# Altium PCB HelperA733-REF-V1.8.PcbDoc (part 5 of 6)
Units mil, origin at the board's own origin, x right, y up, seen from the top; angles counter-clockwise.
Board outline 5905.51 x 4133.86 mil, 2 copper layers (Top, Bottom), stack 12.7 mil thick; 475 components, 355 nets, 1867 pads, 1471 vias.
Unrouted connection lines stored in the file: 1178.
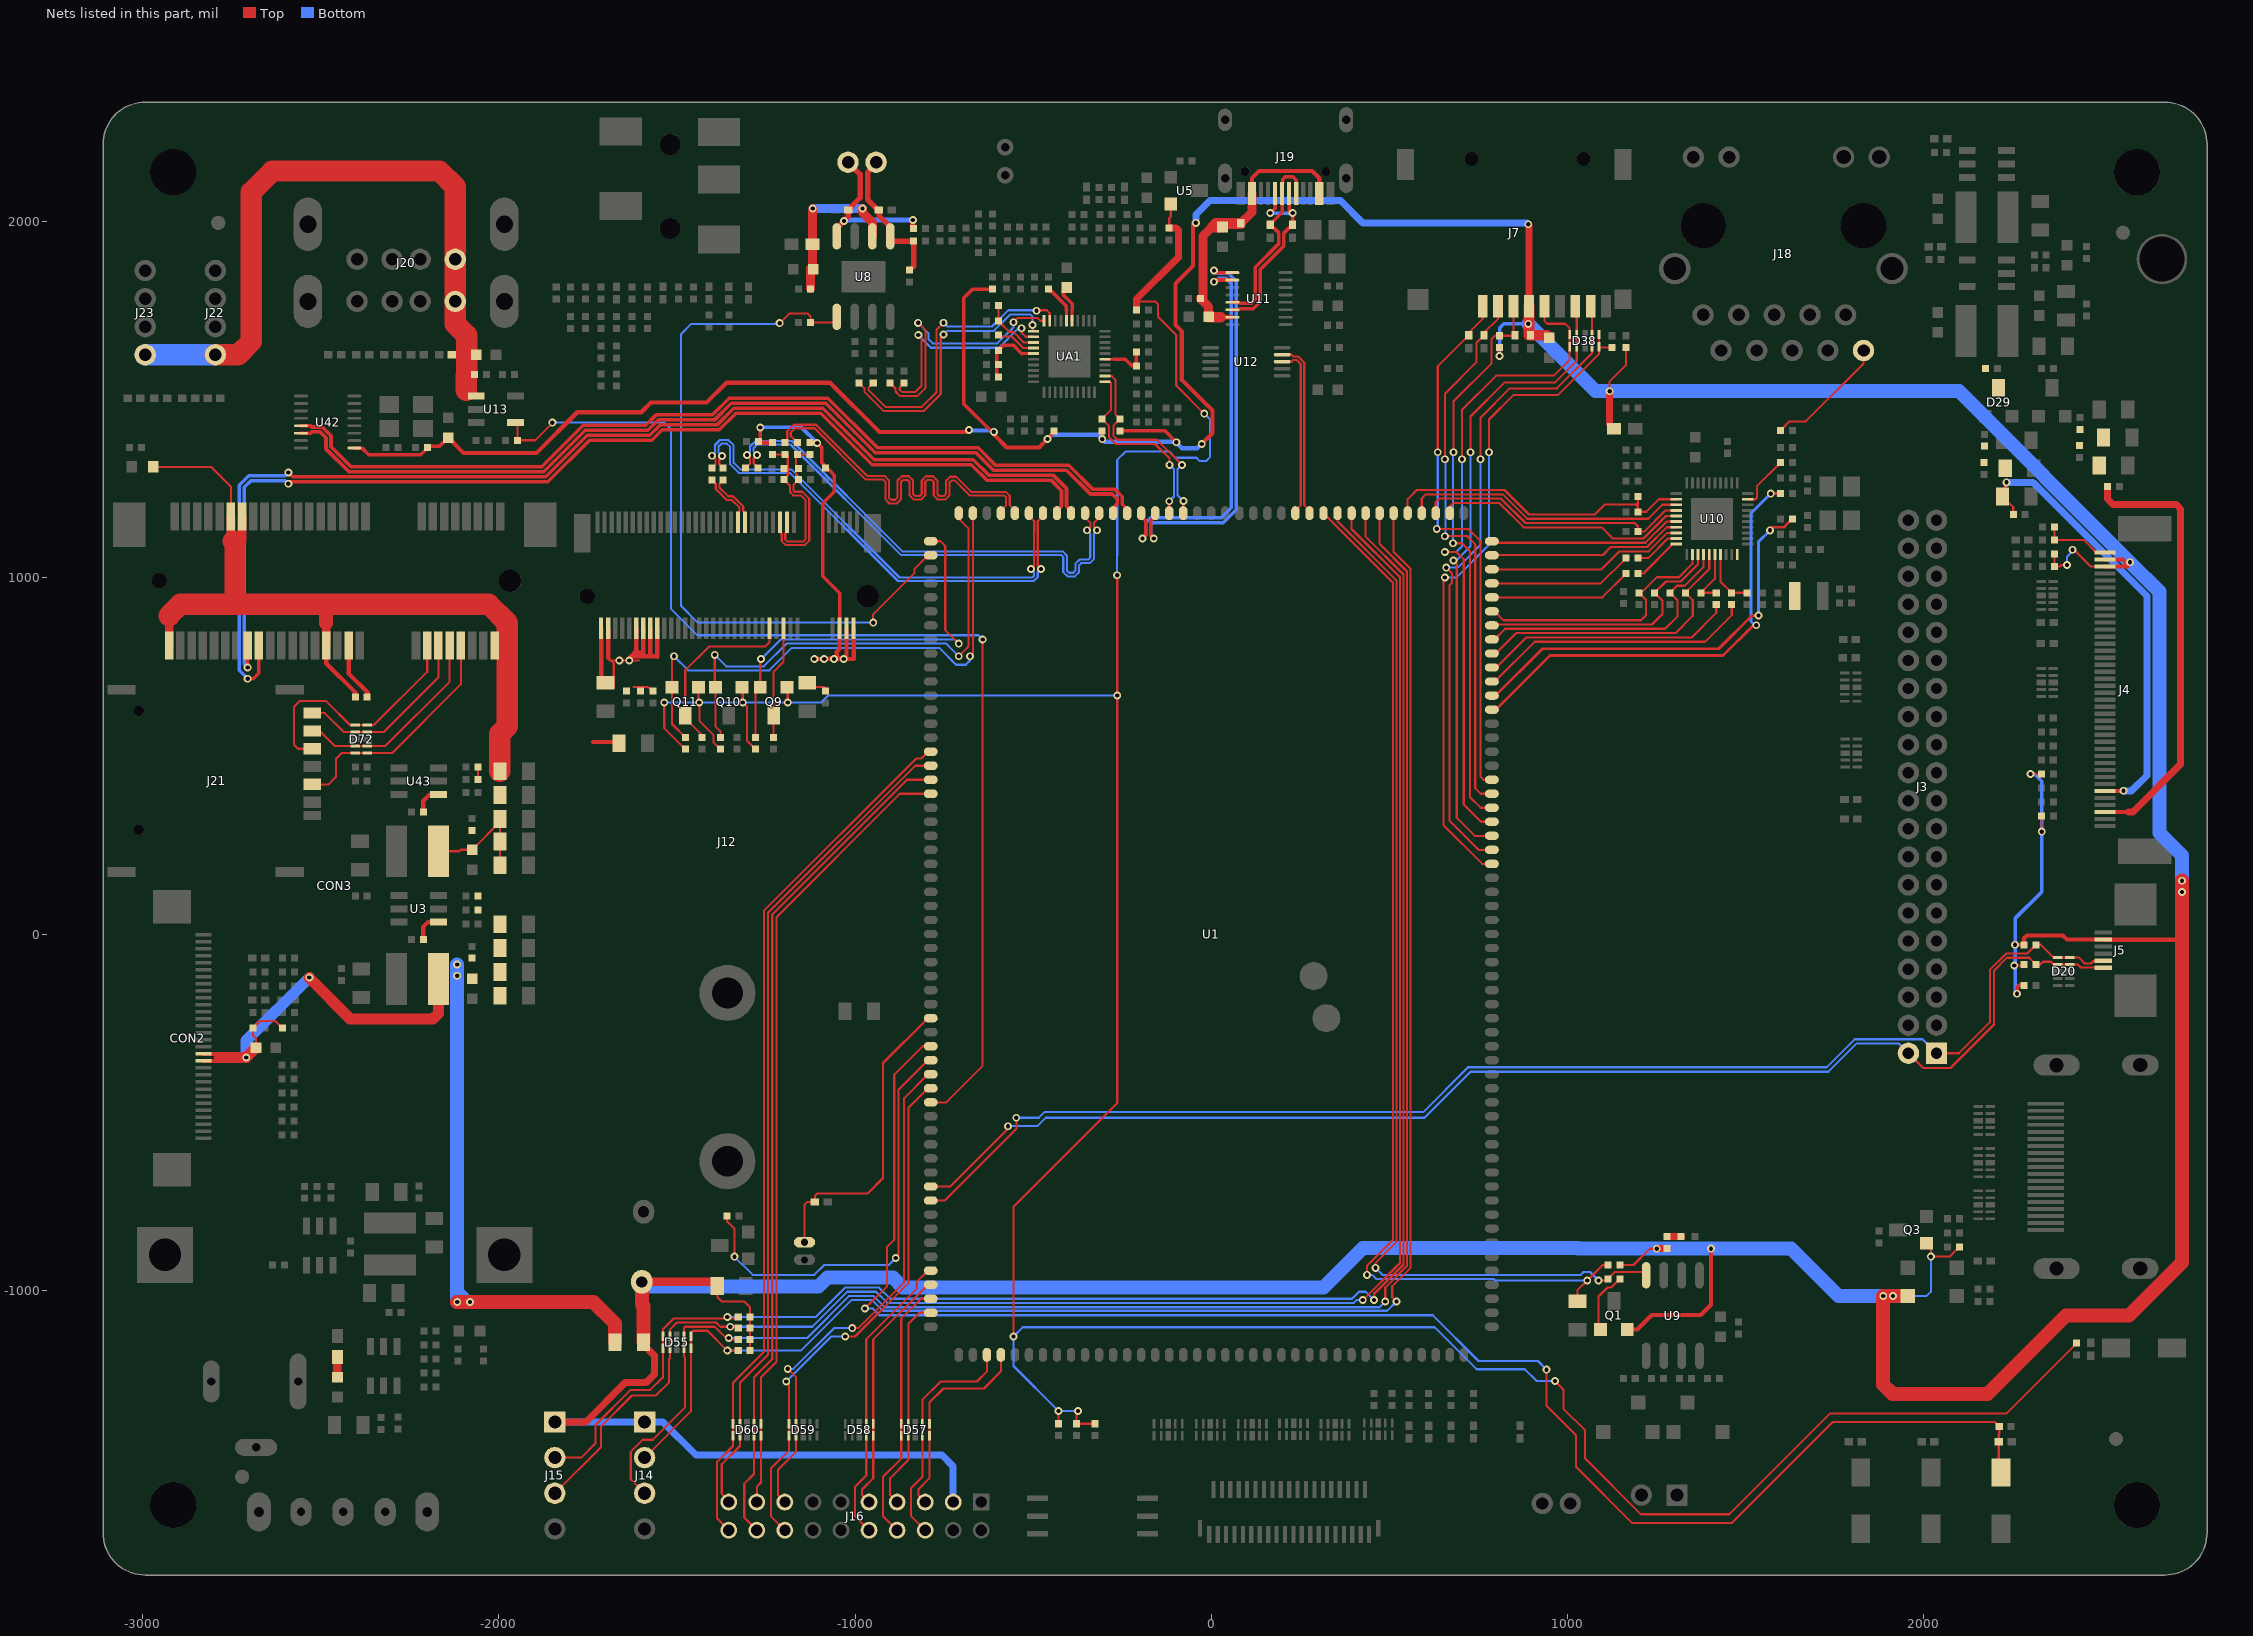
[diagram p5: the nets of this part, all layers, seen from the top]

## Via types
v1: diameter 22, hole 12, Top to Bottom, 1469 vias
v2: diameter 39.37, hole 35.43, Top to Bottom, 2 vias

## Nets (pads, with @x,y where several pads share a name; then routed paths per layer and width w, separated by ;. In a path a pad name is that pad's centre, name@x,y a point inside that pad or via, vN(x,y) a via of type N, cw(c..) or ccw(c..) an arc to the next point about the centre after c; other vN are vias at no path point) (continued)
N18257684: J12.43 R242.2 | length 161.2
  Top w6: R242.2@-1370.08,1274.61 -1380.83,1263.86 -1380.83,1253.48 -1356.04,1228.68 -1342.44,1228.68 -1313.9,1200.15 -1313.9,1187.43 -1309.06,1182.59 J12.43@-1309.06,1155.5
N18257704: J12.41 R243.2 | length 161.5
  Top w6: R243.2@-1401.57,1274.61 -1390.83,1263.86 -1390.83,1248.95 -1360.56,1218.69 -1346.59,1218.69 -1323.9,1196 -1323.9,1187.79 -1328.74,1182.95 J12.41@-1328.74,1155.5
N171758202: Q1.1 R74.1 | length 178.5
  Top w6: Q1.1@1092.42,-1109.87 1086.61,-1109.87 1086.61,-1017.45 1111.93,-992.13 1123.03,-992.13 R74.1@1146.65,-968.5
N171758280: C61.2 R71.1 | length 39.4
  Top w20: C61.2@1279.53,-849.41 R71.1@1318.9,-849.41
N171771995: C8.1 U3.1 | length 84
  Top w11.81: C8.1@-2211.61,-15.75 -2211.61,20.67 -2198.82,33.46 U3.1@-2169.29,33.46
N179147341: C36.2 D29.3
N181483905: C89.1 U43.1 | length 81.2
  Top w11.81: C89.1@-2211.61,342.52 -2211.61,374.02 -2193.9,391.73 U43.1@-2169.29,391.73
N182437470: C322.1 R156.1 | length 56.7
  Top w23.62: C322.1@-2452.76,-1243.7 R156.1@-2452.76,-1187.01
PA-SHDN-PE15: R55.2 U1.133 U8.1 | length 2080.4
  Top w6: v1(-1211.53,1714.62) -1184.75,1741.4 -1132.41,1741.4 -1125,1733.99 R55.2@-1125,1716.54 -1051.07,1716.54 U8.1@-1051.07,1732.16 ; v1(-948.82,874.02) -949.78,874.02 -949.78,896.57 -832.69,1013.66 -832.69,1025.58 -795.28,1062.99 U1.133@-787.4,1062.99
  Bottom w6: v1(-1211.53,1714.62) -1225.16,1712.57 -1459.95,1712.57 -1488.19,1684.33 -1488.19,920.68 -1441.52,874.02 v1(-948.82,874.02)
PA-VDD: C49.1 C51.1 FB1.1 U8.6 | length 457.7
  Top w25: C49.1@-1125,1811.02 -1125,1867.62 -1119.11,1873.51 FB1.1@-1119.11,1936.01 -1119.11,1983.37 -1119.2,1983.46 -1119.2,2026.08 v1(-1118.75,2036.42) ; v1(-979.13,2036.08) -979.76,2026.2 -951.07,1997.51 U8.6@-951.07,1958.16
  Bottom w25: v1(-1118.75,2036.42) -979.13,2036.42 v1(-979.13,2036.08)
PC2: D60.2 D60.9 J16.18 U1.149 | length 2376.8
  Top w6: J16.18@-1275.59,-1673.23 -1311.02,-1637.8 -1311.02,-1543.31 -1283.47,-1515.75 D60.9@-1283.47,-1408.38 D60.2@-1283.47,-1374.3 -1283.47,-1244.09 -1232.28,-1192.91 -1232.28,54.67 -853.88,433.07 U1.149@-787.4,433.07
PC3: D60.5 D60.6 J16.20 U1.147 | length 2459.7
  Top w6: J16.20@-1354.33,-1673.23 -1386.95,-1640.61 -1386.95,-1481.44 -1342.52,-1437.01 -1342.52,-1259.84 -1255.91,-1173.23 -1255.91,65.17 -828.95,492.13 -814.96,492.13 -795.28,511.81 U1.147@-787.4,511.81
PC4: D60.4 D60.7 J16.19 U1.148 | length 2343.8
  Top w6: J16.19@-1354.33,-1594.49 -1354.33,-1590.55 -1374.02,-1570.87 -1374.02,-1488.18 -1322.84,-1437.01 -1322.84,-1259.84 -1244.09,-1181.1 -1244.09,59.75 -831.4,472.44 U1.148@-787.4,472.44
PC12: D60.1 D60.10 J16.17 U1.150 | length 2241.3
  Top w6: J16.17@-1275.59,-1594.49 -1275.59,-1551.18 -1263.78,-1539.37 D60.10@-1263.78,-1408.38 D60.1@-1263.78,-1374.3 -1263.78,-1244.09 -1220.47,-1200.79 -1220.47,47.44 -874.21,393.7 U1.150@-787.4,393.7
PCIE1-REFCLKN: CB11.1 U1.128 | length 1067.2
  Top w6: CB11.1@-1161.42,1378.94 -1180.24,1397.76 -1180.24,1407.46 -1168.24,1419.46 -1113.69,1419.46 -969.64,1275.41 -920.86,1275.41 -914.86,1269.41 -914.86,1220.12 -903.01,1208.26 -882.72,1208.26 -870.86,1220.12 -870.86,1268.75 -864.86,1274.75 -852.86,1274.75 -846.86,1268.75 -846.86,1231.08 -835.01,1219.22 -814.72,1219.22 -802.86,1231.08 -802.86,1268.75 -796.86,1274.75 -784.86,1274.75 -778.86,1268.75 -778.86,1231.08 -767.01,1219.22 -746.72,1219.22 -734.86,1231.08 -734.86,1267.28 -728.86,1273.28 -720.49,1273.28 -689.73,1242.52 -689.53,1242.52 -678.01,1231 -581.18,1231 -575.87,1225.69 -575.87,1203.66 -590.55,1188.98 U1.128@-590.55,1181.1
PCIE1-REFCLKP: CB10.1 U1.127 | length 1094.5
  Top w6: CB10.1@-1196.85,1378.94 -1190.24,1385.55 -1190.24,1411.6 -1172.37,1429.47 -1109.54,1429.47 -965.48,1285.41 -916.72,1285.41 -904.86,1273.55 -904.86,1224.74 -898.86,1218.74 -886.86,1218.74 -880.86,1224.74 -880.86,1272.89 -869.01,1284.75 -848.72,1284.75 -836.86,1272.89 -836.86,1235.22 -830.86,1229.22 -818.86,1229.22 -812.86,1235.22 -812.86,1272.89 -801.01,1284.75 -780.72,1284.75 -768.86,1272.89 -768.86,1235.22 -762.86,1229.22 -750.86,1229.22 -744.86,1235.22 -744.86,1271.42 -733.01,1283.28 -716.15,1283.28 -673.87,1241 -576.83,1241 -565.87,1230.04 -565.87,1203.66 -551.18,1188.98 U1.127@-551.18,1181.1
PCIE1-RXN: R243.1 U1.126 | length 1357.4
  Top w6: R243.1@-1401.57,1308.07 -1391.22,1318.42 -1391.22,1332.17 v1(-1401.57,1342.52) ; U1.126@-511.81,1181.1 -511.81,1173.23 -497.13,1158.54 -497.13,1127.28 -497.13,1033.28 v1(-506.13,1024.28)
  Bottom w6: v1(-1401.57,1342.52) -1393.08,1351.01 -1393.08,1372.53 -1379.08,1386.53 -1355.71,1386.53 -1340.68,1371.5 -1340.68,1322.59 -1322.35,1304.26 -1178.67,1304.26 -875.13,1000.72 -502.73,1000.72 -497.13,1006.32 -497.13,1015.28 v1(-506.13,1024.28)
PCIE1-RXP: R242.1 U1.125 | length 1357.1
  Top w6: v1(-1373.37,1341.5) -1381.01,1333.86 -1381.01,1319.01 R242.1@-1370.08,1308.07 ; v1(-478.13,1024.28) -487.13,1033.28 -487.13,1123.13 -487.13,1158.54 -472.44,1173.23 U1.125@-472.44,1181.1
  Bottom w6: v1(-1373.37,1341.5) -1383.07,1351.2 -1383.07,1368.36 -1374.9,1376.53 -1359.85,1376.53 -1350.68,1367.36 -1350.68,1318.38 -1326.56,1294.26 -1182.81,1294.26 -879.18,990.63 -498.67,990.63 -487.13,1002.17 -487.13,1015.28 v1(-478.13,1024.28)
PCIE1-TXN: CB5.1 U1.122 | length 1379.4
  Top w6: CB5.1@-1307.09,1308.07 -1294.39,1320.76 -1294.39,1335.75 v1(-1303.37,1344.73) ; U1.122@-354.33,1181.1 -354.33,1169.35 -339.32,1154.34 -339.32,1142.53 v1(-348.65,1133.21)
  Bottom w6: v1(-1303.37,1344.73) -1294.71,1353.39 -1294.71,1368.39 -1279.1,1384 -1177.03,1384 -867.11,1074.08 -417.25,1074.08 -405.39,1062.22 -405.39,1020.16 -399.39,1014.16 -387.39,1014.16 -381.39,1020.16 -381.39,1039.17 -369.53,1051.03 -344.98,1051.03 -339.65,1056.37 -339.65,1124.21 v1(-348.65,1133.21)
PCIE1-TXP: CB4.1 U1.121 | length 1379.8
  Top w6: v1(-1275.37,1344.73) -1284.37,1335.73 -1284.37,1320.79 CB4.1@-1271.65,1308.07 ; v1(-320.65,1133.21) -329.1,1141.67 -329.1,1154.72 -314.96,1168.87 U1.121@-314.96,1181.1
  Bottom w6: v1(-1275.37,1344.73) -1284.66,1354.02 -1284.66,1364.28 -1274.94,1374 -1181.17,1374 -871.24,1064.07 -818.14,1064.07 -421.39,1064.08 -415.39,1058.08 -415.39,1015.6 -403.53,1003.74 -383.25,1003.74 -371.39,1015.6 -371.39,1035.03 -365.39,1041.03 -340.84,1041.03 -329.65,1052.22 -329.65,1124.21 v1(-320.65,1133.21)
PCIE-3V3: C11.1 C12.1 C13.1 C26.2 C27.1 C88.1 C95.1 C96.1 C97.1 C98.1 CB1.2 CB2.2 CB3.2 CB6.2 CB7.2 CB8.2 CB9.2 CON2.12 CON2.13 D84.1 J12.2 J12.4 J12.12 J12.14 J12.16 J12.18 J12.70 J12.72 J12.74 L2.2 R9.1 R19.2 R119.2 R236.1 R237.1 | length 5206.5
  Top w6: C27.1@-2681.5,-318.9 -2681.5,-293.01 -2689.96,-284.55 C26.2@-2689.96,-263.78 -2670.28,-244.09 -2626.97,-244.09 R19.2@-2607.28,-263.78 ; -1712.6,728.74 -1695,711.14 -1677.17,693.31 -1677.17,759.84 -1685.04,767.72 ; -1692.92,775.6 -1685.04,767.72 ; -1688.98,767.72 -1685.04,767.72 ; v1(-1633.86,767.72) v1(-1661.42,767.72) -1685.04,767.72 ; v1@-1630.63,767.72 -1606.3,767.72 ; -1622.05,693.31 -1582.09,693.31 CB6.2@-1566.93,682.09 ; CB3.2@-1133.86,693.31 -1087.01,693.31 -1075.79,682.09 CB1.2@-1082.68,682.09
  Top w10: -1736.33,538.91 -1665.52,538.91 D84.1@-1662.05,535.43 ; CB9.2@-1270.67,1381.89 -1265.85,1381.89 v1(-1265.85,1421.82) ; R236.1@-1233.87,1380.53 R236.1@-1232.28,1378.94 ; R237.1@-1125.98,1378.94 R237.1@-1123.32,1378.94 ; v1(-1106.3,1377.95) -1092.87,1364.52 -1092.87,1323 CB8.2@-1080.31,1310.44 ; CB8.2@-1082.68,1308.07 -1080.31,1308.07 CB8.2@-1080.31,1310.44 ; J12.70@-1043.31,858.26 -1043.31,956.7 -1090.55,1003.94 -1090.55,1208.66 -1057.9,1241.31 -1057.9,1288.03 -1071.54,1301.67 ; CB8.2@-1080.31,1310.44 -1071.54,1301.67 ; CB8.2@-1080.31,1310.44 -1071.54,1301.67
  Top w11.81: CON2.12@-2828.74,-356.3 -2783.46,-356.3 -2783.46,-346.46 -2783.46,-336.61 CON2.13@-2828.74,-336.61 ; CB9.2@-1270.67,1381.89 -1270.67,1378.94 R236.1@-1232.28,1378.94 ; R237.1@-1125.98,1378.94 -1125.98,1377.95 v1(-1106.3,1377.95)
  Top w12: -1712.6,728.74 J12.2@-1712.6,858.26 ; -1692.92,775.6 J12.4@-1692.92,858.26 ; v1(-1633.86,767.72) -1630.63,767.72 v1@-1630.63,771.82 ; J12.12@-1614.18,858.26 -1614.18,793.82 -1628.76,779.24 ; J12.14@-1594.49,858.26 -1594.49,789.72 -1612.74,789.72 -1623.22,779.24 ; J12.16@-1574.81,858.26 -1574.81,779.24 ; J12.18@-1555.12,858.26 -1555.12,778.47 -1555.89,779.24 -1574.81,779.24 ; v1(-1114.17,771.65) v1@-1114.17,767.91 ; J12.70@-1043.31,858.26 -1043.31,799.74 -1051.18,791.87 v1@-1051.18,774.14 ; J12.72@-1023.62,858.26 -1023.62,775.59 -1031.68,775.17 v1@-1051.18,774.14 ; J12.74@-1003.94,858.26 -1003.94,771.65 v1(-1031.5,771.65) v1@-1051.18,771.65 ; v1@-1630.63,771.82 -1623.22,779.24 ; v1@-1630.63,771.82 -1630.63,777.36 -1628.76,779.24 ; -1628.76,779.24 -1623.22,779.24 ; -1623.22,779.24 -1574.81,779.24 ; v1@-1114.17,767.91 -1114.17,767.72 -1114.36,767.72 v1@-1114.17,767.91 ; v1@-1114.17,767.91 -1110.43,771.65 -1098.43,771.65 ; -1098.43,771.65 -1086.65,772.27 -1059.16,773.72 v1@-1051.18,774.14 ; -1098.43,771.65 v1(-1086.61,771.65) v1(-1059.06,771.65) v1@-1051.18,771.65 ; v1@-1051.18,771.65 v1@-1051.18,774.14
  Top w31.5: -2783.46,-346.46 v1@-2709.06,-346.46 ; v1(-2708.66,-346.46) -2708.86,-346.26 -2709.06,-346.06 v1@-2709.06,-346.46 ; C27.1@-2681.5,-318.9 v1@-2709.06,-346.46 ; v1(-2531.5,-122.05) -2531.5,-123.91 -2416.84,-238.57 -2185.16,-238.57 -2169.29,-222.7 L2.2@-2169.29,-125.98
  Top w39.37: v1(-2116.6,-1032.69) v1(-2080.6,-1032.69) -1734.7,-1032.69 -1673.86,-1093.53 R119.2@-1673.86,-1145.67
  Bottom w6: v1@-1088.01,768.3 v1(-1086.61,771.65) v1(-1059.06,771.65) v1(-1031.5,771.65)
  Bottom w10: v1(-1265.85,1421.82) -1150.16,1421.82 v1(-1106.3,1377.95)
  Bottom w31.5: v1(-2708.66,-346.46) -2708.66,-299.21 v1(-2531.5,-122.05)
  Bottom w39.37: v1(-2116.73,-85.29) -2116.6,-85.42 -2116.6,-1004.69 ; v1(-2080.6,-1032.69) v1@-2088.6,-1032.69 ; -2116.6,-1004.69 v1@-2088.6,-1032.69 ; -2116.6,-1004.69 v1(-2116.6,-1032.69) v1@-2088.6,-1032.69
  other v1: -2116.73,-117.29
PCIE-CLKREQN: Q10.2 R229.2 U1.131 | length 1401.8
  Top w6: v1(-1393.7,783.46) -1393.7,700.79 -1391.83,698.92 Q10.2@-1391.83,692.54 -1391.83,582.82 -1377.95,568.94 R229.2@-1377.95,552.16 ; v1(-708.66,779.53) -685.04,803.15 -685.04,803.32 -681.1,807.26 -681.1,1137.8 -708.66,1165.35 U1.131@-708.66,1181.1
  Bottom w6: v1(-1393.7,783.46) -1361.35,751.11 -1256.04,751.11 -1192.19,814.96 -744.09,814.96 v1(-708.66,779.53)
PCIE-PERSTN: Q11.2 R231.2 U1.130 | length 1559.8
  Top w6: v1(-1507.87,779.53) -1513.88,773.52 Q11.2@-1513.88,692.54 -1513.88,589.66 R231.2@-1476.38,552.16 ; v1(-677.17,779.53) -669.29,787.4 U1.130@-669.29,1181.1
  Bottom w6: v1(-1507.87,779.53) -1468.32,739.97 -1240.34,739.97 -1177.17,803.15 -763.78,803.15 -716.54,755.91 -688.98,755.91 -677.17,767.72 v1(-677.17,779.53)
PCIE-WAKEN: Q9.2 R120.2 U1.132 | length 1152.9
  Top w6: R120.2@-1279.53,552.16 -1279.53,678.86 Q9.2@-1265.85,692.54 -1265.85,773.52 -1263.78,775.59 v1(-1263.78,771.65) ; U1.132@-787.4,1102.36 -759.84,1102.36 -746.56,1089.08 -746.56,852.86 v1(-708.66,814.96)
  Bottom w6: v1(-1263.78,771.65) -1208.66,826.77 -720.47,826.77 v1(-708.66,814.96)
PERSTN: J12.50 Q11.3 R232.2 | length 515.8
  Top w6: R232.2@-1429.13,552.16 -1433.07,556.1 -1433.07,562.24 -1476.38,605.54 Q11.3@-1476.38,612.54 -1476.38,740.16 -1409.45,807.09 -1251.97,807.09 -1240.16,818.89 J12.50@-1240.16,858.26
PHYRSTB: CE7.2 RE2.2 U1.99 U10.12 | length 918.3
  Top w6: U1.99@551.18,1181.1 551.18,1220.47 576.98,1246.27 822.94,1246.27 891.79,1177.42 1076.01,1177.42 1104.08,1205.5 1191.94,1205.5 ; RE2.2@1197.83,1228.35 1197.83,1211.25 ; U10.12@1305.12,1220.47 1256.38,1220.47 1220.95,1185.04 CE7.2@1197.83,1185.04 1197.83,1199.6 ; 1191.94,1205.5 1197.83,1199.6 ; 1191.94,1205.5 1192.77,1205.5 ; 1192.77,1205.5 1197.83,1205.5 ; 1192.77,1205.5 1192.77,1206.18 1197.83,1211.25 ; 1197.83,1199.6 1197.83,1205.5 ; 1197.83,1205.5 1197.83,1211.25
PK10: D57.5 D57.6 J16.8 U1.186 | length 737.5
  Top w6: J16.8@-881.89,-1673.23 -921.26,-1633.86 -921.26,-1523.62 -870.08,-1472.44 D57.6@-870.08,-1408.38 D57.5@-870.08,-1374.3 -870.08,-1078.74 -814.96,-1023.62 U1.186@-787.4,-1023.62
PK11: D57.4 D57.7 J16.7 U1.187 | length 605.4
  Top w6: J16.7@-881.89,-1594.49 -901.57,-1574.8 -901.57,-1527.56 -850.4,-1476.38 D57.7@-850.4,-1408.38 D57.4@-850.4,-1374.3 -850.4,-1094.49 -818.9,-1062.99 U1.187@-787.4,-1062.99
PK12: D58.2 D58.9 J16.10 U1.184 | length 837.3
  Top w6: J16.10@-960.63,-1673.23 -1000,-1633.86 -1000,-1551.18 -968.51,-1519.69 D58.9@-968.51,-1408.38 D58.2@-968.51,-1374.3 -968.51,-1137.8 -826.77,-996.06 -826.77,-976.38 -795.28,-944.88 U1.184@-787.4,-944.88
PK13: D58.1 D58.10 J16.9 U1.185 | length 706.1
  Top w6: J16.9@-960.63,-1594.49 -980.31,-1574.8 -980.31,-1559.06 -948.82,-1527.56 D58.10@-948.82,-1408.38 D58.1@-948.82,-1374.3 -948.82,-1137.8 U1.185@-795.28,-984.25 ; U1.185@-798.47,-984.25 U1.185@-795.28,-984.25 ; U1.185@-787.4,-984.25 U1.185@-795.28,-984.25
PK16: D57.2 D57.9 J16.6 U1.3 | length 656.7
  Top w6: J16.6@-803.15,-1673.23 -842.52,-1633.86 -842.52,-1555.12 -810.71,-1523.31 -810.71,-1464.57 -811.03,-1464.25 D57.9@-811.03,-1408.38 D57.2@-811.03,-1374.3 -811.03,-1307.09 -759.84,-1255.91 -657.48,-1255.91 -629.92,-1228.35 U1.3@-629.92,-1181.1
PK17: D57.1 D57.10 J16.5 U1.4 | length 583.8
  Top w6: J16.5@-803.15,-1594.49 -821.97,-1575.66 -821.97,-1558.19 -791.34,-1527.56 D57.10@-791.34,-1408.38 D57.1@-791.34,-1374.3 -791.34,-1314.96 -751.83,-1275.45 -637.93,-1275.45 -590.55,-1228.07 U1.4@-590.55,-1181.1
PL12: D59.5 D59.6 J16.16 U1.171 | length 1492.7
  Top w6: J16.16@-1196.85,-1673.23 -1236.22,-1633.86 -1236.22,-1500 -1185.04,-1448.82 D59.6@-1185.04,-1408.38 -1185.04,-1263.78 v1(-1192.91,-1255.91) ; v1(-1027.56,-1129.92) -1000,-1129.92 -850.39,-980.32 -850.39,-488.19 -795.28,-433.07 U1.171@-787.4,-433.07
  Bottom w6: v1(-1192.91,-1255.91) -1066.93,-1129.92 v1(-1027.56,-1129.92)
PL13: D59.4 D59.7 J16.15 U1.170 | length 1459
  Top w6: J16.15@-1196.85,-1594.49 -1215.67,-1575.66 -1215.67,-1503.07 -1165.36,-1452.76 -1165.36,-1244.09 v1(-1188.98,-1220.47) ; v1(-1007.87,-1106.3) -991.4,-1106.3 -862.2,-977.1 -862.2,-460.63 -795.28,-393.7 U1.170@-787.4,-393.7
  Bottom w6: v1(-1188.98,-1220.47) -1173.23,-1220.47 -1059.06,-1106.3 v1(-1007.87,-1106.3)
PM5-BEEP: R81.1 U1.169 | length 1216.8
  Top w6: R81.1@-1359.25,-791.34 -1359.25,-806.1 -1338.58,-826.77 v1(-1338.58,-905.51) ; v1(-885.83,-909.45) -877.95,-901.57 -877.95,-437.01 -795.28,-354.33 U1.169@-787.4,-354.33
  Bottom w6: v1(-1338.58,-905.51) -1287.4,-956.69 -1114.17,-956.69 -1086.61,-929.13 -905.51,-929.13 v1(-885.83,-909.45)
PWRON: C46.1 D41.2 K2.2 U1.168 | length 4639.3
  Top w6: v1(-972.44,-1051.18) -909.76,-988.5 -909.76,-878.27 -889.76,-858.27 -889.76,-394.64 -810.09,-314.96 U1.168@-787.4,-314.96 ; v1(941.01,-1222.65) 941.01,-1324.02 1023.62,-1406.63 1023.62,-1495.32 1181.84,-1653.54 1460.04,-1653.54 1743.66,-1369.93 2199.65,-1369.93 C46.1@2211.61,-1381.89 2211.61,-1402.83 2210.35,-1404.1 D41.2@2210.35,-1425.2 2210.35,-1505.62 K2.2@2216.54,-1511.81 K2.2@2216.54,-1499.02
  Bottom w6: v1(-972.44,-1051.18) -950.35,-1051.18 -931.42,-1070.12 621.72,-1070.12 750.15,-1198.55 916.91,-1198.55 v1(941.01,-1222.65)
REFCLKN: CB11.2 J12.53 R235.1 R237.2 R333.1 | length 480.1
  Top w6: J12.53@-1210.63,1155.5 -1210.63,1128.32 -1205.79,1123.48 -1205.79,1102.82 -1195.1,1092.13 -1140.31,1092.13 -1128.28,1104.16 -1128.28,1221.66 -1147.86,1241.24 -1169.44,1241.24 -1172.29,1244.09 -1172.29,1261.76 R333.1@-1158.46,1275.59 -1165.35,1275.59 R235.1@-1165.35,1306.1 ; R237.2@-1125.98,1345.47 CB11.2@-1161.42,1345.47 -1165.35,1341.54 R235.1@-1165.35,1307.09 ; R235.1@-1165.35,1306.1 R235.1@-1164.37,1307.09 ; R235.1@-1165.35,1306.1 R235.1@-1165.35,1307.09 ; R235.1@-1165.35,1307.09 R235.1@-1164.37,1307.09 ; R235.1@-1164.37,1307.09 R235.1@-1158.46,1307.09 -1161.42,1310.04 R235.1@-1164.37,1307.09
REFCLKP: CB10.2 J12.55 R234.1 R236.2 R334.1 | length 457.8
  Top w6: R236.2@-1232.28,1345.47 CB10.2@-1196.85,1345.47 -1188.98,1345.47 -1188.98,1310.04 -1196.85,1310.04 R234.1@-1199.8,1307.09 -1188.98,1307.09 -1188.98,1286.75 -1195.75,1279.97 -1195.75,1275.59 R334.1@-1199.8,1275.59 -1182.29,1258.08 -1182.29,1239.9 -1173.63,1231.24 -1152.01,1231.24 -1138.54,1217.78 -1138.54,1108.04 -1144.45,1102.13 -1190.96,1102.13 -1195.79,1106.96 -1195.79,1123.89 -1190.95,1128.73 J12.55@-1190.95,1155.5
REGOUT: L6.1 U10.30
RGMII0-CLK-25M: R86.1 U1.82 | length 1269.3
  Top w8: U1.82@787.4,629.92 799.12,629.92 950.56,781.36 1436.25,781.36 1521.65,866.76 v1(1529.67,866.76) ; v1(1570.14,1236.04) 1570.14,1236.22 R86.1@1597.44,1236.22
  Bottom w8: v1(1529.67,866.76) 1528.89,865.32 1525.24,867.29 1515.15,877.39 1515.15,1181.05 v1(1570.14,1236.04)
RGMII0-CLKIN-125M: RE12.1 U1.83 | length 1170.4
  Top w8: U1.83@787.4,669.29 797.97,669.29 929.32,800.63 1424.1,800.63 1517.47,894.01 v1(1536.2,894.01) ; v1(1568.12,1132.92) 1577.1,1141.9 1607.81,1141.9 1617.76,1151.84 1617.76,1152.21 RE12.1@1630.91,1165.35
  Bottom w8: v1(1536.2,894.01) 1536.2,1101 v1(1568.12,1132.92)
RGMII0-MDC: U1.98 U10.13 | length 805.3
  Top w6: U1.98@590.55,1181.1 590.55,1222.22 602.36,1234.04 818.2,1234.04 886.82,1165.42 1226.4,1165.42 1265.71,1204.72 U10.13@1305.12,1204.72
RGMII0-MDIO: RE3.2 U1.97 U10.14 | length 781.6
  Top w6: U1.97@629.92,1181.1 629.92,1212.6 639.31,1221.99 813.28,1221.99 881.85,1153.42 1188.27,1153.42 1197.83,1143.86 RE3.2@1197.83,1129.92 1215.38,1129.32 1275.03,1188.98 U10.14@1305.12,1188.98
RGMII0-RXCK: RE10.1 U1.84 | length 779.7
  Top w6: U1.84@787.4,708.66 795.89,708.66 907.67,820.44 1386.15,820.44 1460.63,894.92 RE10.1@1460.63,924.21
RGMII0-RXCTL: RE11.1 U1.85 | length 716.3
  Top w6: U1.85@787.4,748.03 799.33,748.03 883.74,832.44 1348.36,832.44 1417.32,901.4 RE11.1@1417.32,924.21
RGMII0-RXD0: RE9.1 U1.86 U10.25 | length 815.7
  Top w6: U1.86@787.4,787.4 798.33,787.4 855.39,844.46 1302.75,844.46 1351.17,892.87 1351.17,937.22 RE9.1@1330.71,957.68 1397.64,1024.61 U10.25@1397.64,1064.96
RGMII0-RXD1: RE8.1 U1.87 U10.24 | length 782.1
  Top w6: U1.87@787.4,826.77 795.09,826.77 825.13,856.81 1273.57,856.81 1309,892.24 1309,936.08 RE8.1@1287.4,957.68 1307.24,977.51 1328.69,977.51 1381.89,1030.71 U10.24@1381.89,1064.96
RGMII0-RXD2: RE5.1 U1.88 U10.23 | length 743.1
  Top w6: U1.88@787.4,866.14 790.08,868.82 1237.09,868.82 1266.43,898.16 1266.43,935.34 RE5.1@1244.09,957.68 1276.45,989.51 1317.55,989.51 1366.14,1038.1 U10.23@1366.14,1064.96
RGMII0-RXD3: RE13.1 U1.89 U10.22 | length 728.8
  Top w6: U1.89@787.4,905.51 789.03,903.88 796.7,903.88 819.75,880.82 1206.14,880.82 1220.29,894.97 1220.29,938.18 RE13.1@1200.79,957.68 1206.83,957.68 1250.67,1001.52 1312.59,1001.52 1350.39,1039.33 U10.22@1350.39,1064.96
RGMII0-TXCK: RE7.1 U1.90 | length 404.7
  Top w6: U1.90@787.4,944.88 1097.44,944.88 RE7.1@1164.37,1011.81
RGMII0-TXCTL: RE6.1 U1.91 | length 406.3
  Top w6: U1.91@787.4,984.25 1093.5,984.25 RE6.1@1164.37,1055.12
RGMII0-TXD0: U1.92 U10.18 | length 560.1
  Top w6: U1.92@787.4,1023.62 1095.38,1023.62 1145.74,1073.98 1227.91,1073.98 1279.92,1125.98 U10.18@1305.12,1125.98
RGMII0-TXD1: U1.93 U10.17 | length 550.3
  Top w6: U1.93@787.4,1062.99 788.22,1063.81 1099.24,1063.81 1121.48,1086.05 1223.01,1086.05 1278.7,1141.73 U10.17@1305.12,1141.73
RGMII0-TXD2: U1.94 U10.16 | length 544.1
  Top w6: U1.94@787.4,1102.36 791.71,1098.05 1218.04,1098.05 1277.47,1157.48 U10.16@1305.12,1157.48
RGMII0-TXD3: U1.96 U10.15 | length 726.3
  Top w6: U1.96@669.29,1181.1 669.29,1199.99 679.28,1209.98 808.32,1209.98 876.9,1141.4 1095.65,1141.4 1126.85,1110.2 1213.22,1110.2 1276.25,1173.23 U10.15@1305.12,1173.23
RSET: RE4.2 U10.39 | length 153.1
  Top w6: U10.39@1505.91,1220.47 1527.85,1220.47 1531.32,1223.94 1531.32,1256.71 RE4.2@1597.44,1322.83
RTC-IN: D37.2 J8.2 U1.166 | length 875.9
  Top w6: J8.2@-1141.73,-865.16 -1141.73,-759.84 -1133.86,-751.97 D37.2@-1112.49,-751.97 -1112.49,-734.54 -1106.3,-728.35 -964.57,-728.35 -921.26,-685.04 -921.26,-362.2 -795.28,-236.22 U1.166@-787.4,-236.22
RXC/PHYAD1: RE10.2 RE14.2 U10.27 | length 163.6
  Top w6: U10.27@1429.13,1064.96 1429.13,989.17 RE10.2@1460.63,957.68 RE14.2@1503.94,957.68
RXCTL/PHYAD2: RE11.2 RE15.2 U10.26 | length 166.9
  Top w6: U10.26@1413.39,1064.96 1413.39,997.05 RE15.2@1374.02,957.68 1374.54,957.68 RE11.2@1417.32,957.68
S-TWI0-CTP0-SCK: D20.2 D20.9 J3.2 J5.6 R25.1 U1.178 | length 3753.1
  Top w6: -759.84,-708.66 U1.178@-787.4,-708.66 -732.28,-708.66 -570.87,-547.24 v1(-570.87,-539.37) ; J3.2@1956.69,-334.65 1998.03,-375.98 2074.8,-375.98 2196.85,-253.94 2196.85,-102.72 2233.05,-66.53 2295.9,-66.53 R25.1@2314.74,-85.37 2326.81,-85.37 2334.45,-77.73 2356.97,-77.73 2364.61,-85.38 D20.2@2375.45,-85.38 2431.76,-85.38 2440.88,-94.49 J5.6@2503.94,-94.49
  Bottom w6: v1(-570.87,-539.37) -488.19,-539.37 -464.57,-515.75 598.43,-515.75 727.74,-386.43 1732.02,-386.43 1811.47,-306.98 1929.03,-306.98 J3.2@1956.69,-334.65
S-TWI0-CTP0-SDA: D20.1 D20.10 J3.1 J5.5 R24.1 U1.179 | length 3751.6
  Top w6: U1.179@-787.4,-748.03 -748.03,-748.03 -547.24,-547.24 v1(-547.24,-515.75) ; J3.1@2035.43,-334.65 2098.43,-334.65 2185.42,-247.65 2185.42,-100.01 2230.91,-54.53 2290.46,-54.53 R24.1@2314.74,-30.25 2327.97,-30.25 2363.4,-65.68 D20.1@2375.45,-65.68 2434.56,-65.68 2451.56,-82.68 2469.23,-82.68 2476.33,-75.58 2503.94,-75.58 J5.5@2503.94,-74.8
  Bottom w6: v1(-547.24,-515.75) -484.25,-515.75 -468.5,-500 594.49,-500 720.47,-374.02 1727.22,-374.02 1805.96,-295.28 1996.06,-295.28 J3.1@2035.43,-334.65
SDC0-CLK: D38.1 D38.10 J7.5 U1.74 | length 1855.6
  Top w6: v1(655.53,1072.38) 687.82,1072.38 708.43,1051.77 708.43,363.33 756.79,314.96 U1.74@787.4,314.96 ; v1(703.53,1332.38) 703.53,1471.23 799.68,1567.39 961.09,1567.39 1005.91,1612.21 1005.91,1700.45 993.43,1712.92 943.37,1712.92 934.94,1721.35 934.94,1761.81 J7.5@935.04,1761.81
  Bottom w6: v1(655.53,1072.38) 687.53,1072.38 703.53,1088.38 v1(703.53,1332.38)
SDC0-CMD: D35.2 J7.3 R52.2 U1.75 | length 1606.6
  Top w6: v1(678.67,1096.85) 703.49,1096.85 725.99,1074.36 725.99,384.25 755.91,354.33 U1.75@787.4,354.33 ; v1(679.53,1352.38) 679.53,1494.47 786.77,1601.71 786.77,1669.99 795.97,1679.2 R52.2@809.17,1679.2 D35.2@848.43,1679.2 ; J7.3@848.43,1761.81 D35.2@848.43,1679.2 ; D35.2@848.43,1679.2 848.43,1673.51 D35.2@852.48,1680.47 851.21,1679.2 D35.2@848.43,1679.2
  Bottom w6: v1(678.67,1096.85) 678.67,1353.24 v1(679.53,1352.38)
SDC0-D0: D38.2 D38.9 J7.7 U1.73 | length 1791.5
  Top w6: v1(679.53,1048.38) 689.01,1038.9 689.01,326.11 739.53,275.59 U1.73@787.4,275.59 ; v1(727.53,1352.38) 727.53,1452.38 823.53,1548.38 964.99,1548.38 1025.59,1608.98 D38.2@1025.59,1648.23 D38.9@1025.59,1682.68 1025.59,1744.41 1021.65,1748.35 J7.7@1021.65,1761.81
  Bottom w6: v1(679.53,1048.38) 687.53,1048.38 727.53,1088.38 v1(727.53,1352.38)
SDC0-D1: D38.4 D38.7 J7.8 U1.72 | length 1873
  Top w6: v1(659.53,1028.38) 675.59,1012.32 675.59,985.46 669.06,978.94 669.06,317.16 750,236.22 U1.72@787.4,236.22 ; v1(755.53,1332.38) 755.53,1449.01 837.89,1531.37 969.63,1531.37 1068.9,1630.64 D38.4@1068.9,1648.23 D38.7@1068.9,1682.68 1068.9,1735.16 1064.96,1739.1 J7.8@1064.96,1761.81
  Bottom w6: v1(659.53,1028.38) 691.53,1028.38 755.53,1092.38 v1(755.53,1332.38)
SDC0-D2: D33.2 J7.1 U1.77 | length 1516.6
  Top w6: v1(632.73,1137.26) v1@631.92,1136.98 ; v1(635.53,1352.38) 635.53,1593.44 D33.2@722.56,1680.47 722.56,1688.06 761.81,1727.32 J7.1@761.81,1761.81 ; U1.77@787.4,433.07 763.78,433.07 755.91,440.94 755.91,1102.26 721.18,1136.98 v1@631.92,1136.98 ; v1@631.92,1136.98 631.2,1136.98 631.27,1136.76 v1@631.92,1136.98
  Bottom w6: v1(632.73,1137.26) 635.53,1137.26 v1(635.53,1352.38)
SDC0-D3: D34.2 J7.2 U1.76 | length 1544.1
  Top w6: v1(655.53,1116.38) 657.41,1116.96 717.62,1116.96 740.94,1093.64 740.94,408.66 755.91,393.7 U1.76@787.4,393.7 ; v1(655.53,1332.38) 655.95,1332.91 655.95,1516.42 744.09,1604.56 744.09,1658.7 D34.2@765.86,1680.47 763.78,1685.98 805.12,1727.32 J7.2@805.12,1761.81
  Bottom w6: v1(655.53,1116.38) 657.1,1116.98 657.1,1331.76 656,1332.85 v1(655.53,1332.38)
SDC0-DET: D38.5 D38.6 R53.1 U1.71 | length 1867.1
  Top w6: v1(655.53,1000.38) 651.74,996.59 651.74,305.7 760.59,196.85 U1.71@787.4,196.85 ; v1(779.53,1352.38) 779.53,1444 848.65,1513.13 973.39,1513.13 1088.58,1628.32 D38.5@1088.58,1648.23 ; D38.6@1088.58,1682.68 D38.5@1088.58,1648.23 ; R53.1@1124.13,1645.73 1091.08,1645.73 D38.5@1088.58,1648.23
  Bottom w6: v1(655.53,1000.38) 687.53,1000.38 779.53,1092.38 v1(779.53,1352.38)
SPKR+: CA22.1 D45.2 J10.1 U8.8 | length 472.7
  Top w15: U8.8@-1051.07,1958.16 U8.8@-1051.07,1981.15 ; U8.8@-1051.07,1983.16 U8.8@-1051.07,1981.15 ; J10.1@-1019.66,2166.23 -985.63,2132.2 -985.63,2066.44 D45.2@-1019.45,2032.62 -1019.45,2012.77 v1(-1031.05,2001.17) U8.8@-1051.07,1981.15 ; v1(-837.6,2003.98) -837.6,1979.74 -835.63,1979.74 CA22.1@-835.63,1980.31
  Bottom w15: v1(-1031.05,2001.17) -1028.24,2003.98 v1(-837.6,2003.98)
SPKR-: CA25.1 D44.2 J10.2 R58.2 U8.5 | length 413.5
  Top w15: J10.2@-940.92,2166.23 -938.1,2163.42 -964.62,2136.9 -964.62,2061.84 -935.4,2032.62 D44.2@-933.4,2032.62 -931.91,2032.62 -931.91,2015.1 -901.07,1984.27 U8.5@-901.07,1958.16 -901.07,1944.88 CA25.1@-835.63,1944.88 -835.63,1874.02 R58.2@-846.46,1863.19
SPOLN: R59.1 UA1.12 | length 617.1
  Top w6: R59.1@-862.2,1546.26 -874.28,1534.18 -874.28,1527.71 -868.37,1521.8 -830.31,1521.8 -813.86,1538.25 -813.86,1672.83 v1(-822.23,1681.2) ; v1(-533,1700.06) -533,1688.37 -520.84,1676.21 UA1.12@-498.82,1676.21
  Bottom w6: v1(-822.23,1681.2) -786.6,1645.57 -595.74,1645.57 -544.29,1697.01 -536.05,1697.01 v1(-533,1700.06)
SPOLP: R56.1 UA1.11 | length 781.4
  Top w6: R56.1@-988.19,1546.26 -973.75,1531.82 -973.75,1521.68 -919.76,1467.69 -807.58,1467.69 -759.47,1515.8 -759.47,1674.68 v1(-751.47,1682.68) ; v1(-501.55,1709.44) -500.5,1709.4 -500.5,1691.95 UA1.11@-498.82,1691.95
  Bottom w6: v1(-751.47,1682.68) -741.13,1693.02 -610.44,1693.02 -564.54,1738.92 -508.08,1738.92 -501.54,1732.38 v1(-501.55,1709.44) v1@-506.5,1709.4
SPORN: R60.1 UA1.10 | length 748.4
  Top w6: R60.1@-901.57,1546.26 -886.31,1531 -886.31,1522.66 -873.32,1509.67 -825.47,1509.67 -801.85,1533.29 -801.85,1694.36 v1(-822.81,1715.32) ; v1(-555.12,1717.23) -542.91,1729.44 -488.22,1729.44 -480.27,1721.48 UA1.10@-469.3,1721.48
  Bottom w6: v1(-822.81,1715.32) -794.05,1686.56 -794.05,1669.99 -782,1657.94 -600.42,1657.94 -555.12,1703.24 v1(-555.12,1717.23)
SPORP: R57.1 UA1.9 | length 802.5
  Top w6: R57.1@-948.82,1546.26 -961.7,1533.38 -961.7,1526.71 -914.68,1479.69 -812.82,1479.69 -771.48,1521.03 -771.48,1695.8 v1(-751.36,1715.92) ; v1(-490.34,1749.5) -490.34,1750.94 -461.88,1750.94 -453.55,1742.6 UA1.9@-453.55,1721.48
  Bottom w6: v1(-751.36,1715.92) -740.5,1705.06 -615.37,1705.06 -569.49,1750.94 -494.99,1750.94 v1(-490.34,1749.5)
TRM-CTR: C62.2 J18.1 | length 347.9
  Top w6: C62.2@1597.44,1413.39 1623.06,1439 1668.96,1439 1830.71,1600.75 J18.1@1830.71,1637.8
TWI8-SCK: RA22.1 U1.115 UA1.32 | length 578
  Top w6: UA1.32@-298.04,1565.97 -279.29,1565.97 -269.23,1555.91 -269.23,1459.19 RA22.1@-255.91,1445.87 -274.75,1427.02 -274.75,1398.82 -263.42,1387.49 -152.85,1387.49 v1(-82.07,1316.71) ; U1.115@-78.74,1181.1 -78.74,1214.75 v1(-78.26,1215.23)
  Bottom w6: v1(-82.07,1316.71) -94.75,1304.03 -94.75,1231.73 v1(-78.26,1215.23)
TWI8-SDA: RA23.1 U1.116 UA1.31 | length 547.8
  Top w6: UA1.31@-298.04,1550.22 -286.23,1550.22 -281.26,1545.26 -281.26,1471.69 RA23.1@-307.09,1445.87 -286.75,1425.53 -286.75,1393.79 -268.4,1375.44 -157.84,1375.44 -117.02,1334.62 v1(-117.02,1316.85) ; v1(-118.17,1214.55) -118.11,1214.49 U1.116@-118.11,1181.1
  Bottom w6: v1(-118.17,1214.55) -104.75,1227.96 -104.75,1304.58 v1(-117.02,1316.85)
TXC: RE7.2 U10.20 | length 141.5
  Top w6: RE7.2@1197.83,1011.81 1212.92,1011.81 1295.59,1094.49 U10.20@1305.12,1094.49
TXCTL: RE6.2 U10.19 | length 130.1
  Top w6: RE6.2@1197.83,1055.12 1226.02,1055.12 1281.14,1110.24 U10.19@1305.12,1110.24
UART0-RX: U1.107 U12.8 | length 483.6
  Top w6: U12.8@198.82,1606.3 225.44,1606.3 230.28,1611.14 239.61,1611.14 250.91,1599.84 250.91,1203.66 236.22,1188.98 U1.107@236.22,1181.1
UART0-TX: U1.106 U12.9 | length 500.2
  Top w6: U12.9@198.82,1625.98 225.44,1625.98 230.28,1621.14 243.75,1621.14 260.91,1603.99 260.91,1203.66 275.59,1188.98 U1.106@275.59,1181.1
UART2-RX: D51.1 R69.1 U1.105 | length 3018.9
  Top w6: U1.105@314.96,1181.1 509.5,986.56 509.5,-858.83 437.01,-931.33 v1(437.01,-956.69) ; D51.1@1027.56,-1030.87 1027.56,-1000 v1(1055.12,-972.44) 1098.43,-929.13 R69.1@1113.19,-929.13
  Bottom w6: v1(437.01,-956.69) 451.52,-956.69 463.33,-968.5 792.91,-968.5 796.85,-972.44 v1(1055.12,-972.44)
UART2-TX: R74.2 U1.104 U9.4 | length 3007.6
  Top w6: U1.104@354.33,1181.1 354.33,1158.14 519.5,992.96 519.5,-864.9 460.63,-923.77 v1(460.63,-937.01) ; v1(1086.61,-972.44) 1113.19,-972.44 R74.2@1113.19,-968.5 1132.87,-948.82 1211.23,-948.82 U9.4@1220.28,-957.87
  Bottom w6: v1(460.63,-937.01) 480.32,-956.69 1036.99,-956.69 1044.86,-948.82 1062.99,-948.82 v1(1086.61,-972.44)
UART3-RX: D55.2 D55.9 J14.3 R77.2 U1.101 | length 4916.2
  Top w6: J14.3@-1590.55,-1569.69 -1629.55,-1530.68 -1629.55,-1453.53 -1595.71,-1419.69 -1567.82,-1419.69 -1476.78,-1328.65 -1476.78,-1188.57 -1480.32,-1185.04 D55.9@-1480.32,-1162.71 D55.2@-1480.32,-1128.63 -1480.32,-1106.3 -1476.38,-1102.36 -1393.7,-1102.36 v1@-1358.27,-1137.8 ; v1(-1354.33,-1133.86) v1@-1358.27,-1137.8 ; R77.2@-1327.76,-1137.8 v1@-1358.27,-1137.8 ; U1.101@472.44,1181.1 472.44,1094.72 549.5,1017.66 549.5,-931.54 488.19,-992.85 v1(488.19,-1031.5)
  Bottom w6: v1(-1354.33,-1133.86) -1133.86,-1133.86 -1015.75,-1015.75 -948.82,-1015.75 -917.01,-1047.56 472.13,-1047.56 v1(488.19,-1031.5)
UART3-TX: D55.1 D55.10 J14.2 R78.2 U1.100 | length 4794.2
  Top w6: J14.2@-1590.55,-1469.69 -1460.63,-1339.76 D55.10@-1460.63,-1175.8 ; R78.2@-1327.76,-1169.29 v1(-1358.27,-1169.29) -1414.14,-1113.42 -1454.57,-1113.42 -1460.63,-1119.47 D55.1@-1460.63,-1128.63 D55.10@-1460.63,-1162.71 ; U1.100@511.81,1181.1 511.81,1072.32 559.5,1024.63 559.5,-936.56 507.87,-988.19 507.87,-1019.69 v1(519.69,-1031.5) ; D55.10@-1460.63,-1175.8 D55.10@-1460.63,-1162.71 ; D55.10@-1460.63,-1175.8 D55.10@-1460.63,-1162.71
  Bottom w6: v1(-1358.27,-1169.29) -1151.94,-1169.29 -1010.21,-1027.56 -951.75,-1027.56 -921.75,-1057.56 493.62,-1057.56 v1(519.69,-1031.5)
UART4-RX: D55.4 D55.7 J15.3 R79.2 U1.103 | length 4982
  Top w6: J15.3@-1842.52,-1569.69 -1712.6,-1439.76 -1712.6,-1381.89 -1625.98,-1295.28 -1559.06,-1295.28 -1521.65,-1257.87 -1521.65,-1192.74 -1519.69,-1190.78 D55.4@-1519.69,-1128.63 -1519.69,-1110.29 -1499.95,-1090.55 -1389.69,-1090.55 -1377.88,-1102.36 v1(-1350.39,-1102.36) -1327.76,-1102.36 R79.2@-1327.76,-1106.3 ; U1.103@393.7,1181.1 393.7,1136.78 529.5,1000.98 529.5,-923.26 v1(425.2,-1027.56)
  Bottom w6: v1(-1350.39,-1102.36) -1120.08,-1102.36 -1021.65,-1003.94 -940.94,-1003.94 -909.45,-1035.43 400.29,-1035.43 408.16,-1027.56 v1(425.2,-1027.56)
UART4-TX: D55.5 D55.6 J15.2 R80.2 U1.102 | length 4991.8
  Top w6: J15.2@-1842.52,-1469.69 -1768.9,-1469.69 -1728.35,-1429.13 -1728.35,-1377.95 -1629.92,-1279.53 -1574.8,-1279.53 -1541.34,-1246.06 -1539.37,-1246.06 D55.6@-1539.37,-1162.71 ; v1(-1358.27,-1074.8) v1@-1358.27,-1078.74 ; R80.2@-1327.76,-1074.8 -1331.69,-1078.74 v1@-1358.27,-1078.74 ; U1.102@433.07,1181.1 433.07,1115.43 539.5,1009 539.5,-927.4 456.69,-1010.21 v1(456.69,-1027.56) ; D55.6@-1539.37,-1162.71 D55.5@-1539.37,-1141.72 ; D55.6@-1539.37,-1162.71 -1539.37,-1172.53 D55.6@-1539.37,-1162.71 ; D55.5@-1539.37,-1141.72 D55.5@-1539.37,-1128.63 ; D55.5@-1539.37,-1141.72 D55.5@-1539.37,-1128.63 ; D55.5@-1539.37,-1128.63 -1539.37,-1110.24 -1507.87,-1078.74 v1@-1358.27,-1078.74
  Bottom w6: v1(-1358.27,-1074.8) -1110.24,-1074.8 -1027.56,-992.13 -933.07,-992.13 -901.57,-1023.62 394.92,-1023.62 414.61,-1003.94 433.07,-1003.94 v1(456.69,-1027.56)
UPUSB-DM: D62.1 J19.A7 J19.B7 U11.5 | length 541.7
  Top w10: U11.5@59.06,1773.03 77.36,1773.03 79.52,1770.87 113.06,1770.87 123.06,1780.87 123.06,1871.17 189.85,1937.97 189.85,1967.5 166.13,1991.22 D62.1@165.35,1992 ; D62.1@165.35,1990.44 D62.1@165.35,1992 ; J19.B7@238.19,2078.74 238.19,2116.02 228.23,2125.98 208.66,2125.98 200.79,2118.11 198.82,2095.73 J19.A7@198.82,2078.74 198.82,2025.91 165.35,1992.44 D62.1@165.35,1992
UPUSB-DP: D61.1 J19.A6 J19.B6 U11.6 | length 567.2
  Top w10: U11.6@59.06,1752.17 76.85,1752.17 80.09,1755.41 117.64,1755.41 137.12,1774.89 137.12,1865.35 203.85,1932.09 203.85,1967.5 226.57,1990.22 228.35,1988.44 D61.1@228.35,1990.44 228.35,2019.53 218.5,2029.37 J19.A6@218.5,2078.74 ; v1@161.42,2019.68 v1(165.35,2023.62) 179.13,2037.4 J19.B6@179.13,2078.74 ; v1(228.35,2023.62) v1@229.41,2023.62
  Bottom w10: v1(165.35,2023.62) v1(228.35,2023.62)
USB0-DM: U1.117 U11.1 | length 1148.2
  Top w10: v1(-161.42,1110.24) -170.17,1118.98 -170.17,1160.54 -157.48,1173.23 U1.117@-157.48,1181.1 ; v1(7.87,1862.2) 13.58,1856.5 U11.1@59.06,1856.5
  Bottom w10: v1(-161.42,1110.24) -170.17,1118.98 -170.17,1148.34 -164.08,1154.42 33.36,1154.42 69.99,1191.05 69.99,1831.58 47.24,1854.33 15.75,1854.33 v1(7.87,1862.2)
USB0-DP: U1.118 U11.2 | length 1127
  Top w10: U1.118@-196.85,1181.1 -196.85,1173.23 -184.17,1160.54 -184.17,1118.98 v1(-192.91,1110.24) ; v1(7.87,1830.71) 12.8,1835.63 U11.2@59.06,1835.63
  Bottom w10: v1(-192.91,1110.24) -184.17,1118.98 -184.17,1154.14 -169.88,1168.42 27.56,1168.42 55.99,1196.85 55.99,1825.78 41.45,1840.33 21.43,1840.33 9.84,1828.74 v1(7.87,1830.71)
USB1-DM: U1.119 U42.5 | length 2617.8
  Top w10: U42.5@-2555.12,1426.57 -2527.56,1426.57 -2524.13,1423.14 -2495.23,1423.14 -2470.82,1398.73 -2470.82,1367.22 -2414.64,1311.05 -1879.7,1311.05 -1762.94,1427.81 -1587.62,1427.81 -1558.51,1456.92 -1479.42,1456.92 ; -1479.42,1456.92 -1400.33,1456.92 -1353.24,1504.01 -1076.3,1504.01 -937.13,1364.83 -654.45,1364.83 -605.74,1316.13 -400.49,1316.13 -333.31,1248.95 -271.72,1248.95 -249.78,1227.01 -249.78,1206.06 -236.22,1192.5 U1.119@-236.22,1181.1
USB1-DP: U1.120 U42.6 | length 2593.2
  Top w10: U42.6@-2555.12,1405.71 -2527.56,1405.71 -2524.13,1409.14 -2501.03,1409.14 -2484.82,1392.93 -2484.82,1361.42 -2420.44,1297.05 -1873.59,1297.05 -1756.89,1413.75 -1581.83,1413.75 -1552.66,1442.92 -1394.22,1442.92 -1347.21,1489.93 -1082.1,1489.93 -943.01,1350.83 -660.25,1350.83 -611.54,1302.13 -406.33,1302.13 -339.15,1234.95 -277.58,1234.95 -264.53,1221.9 -264.53,1207.68 -275.59,1196.62 U1.120@-275.59,1181.1
USB2-DM: CON3.36 U1.123 | length 3258
  Top w10: v1(-2704.72,716.54) -2688.98,716.54 -2673.23,732.28 CON3.36@-2673.23,810.04 ; v1(-2590.55,1295.28) -2578.32,1283.05 -1867.79,1283.05 -1751.2,1399.64 -1590.92,1399.64 -1576.15,1399.64 -1546.87,1428.92 -1387.34,1428.92 -1340.56,1475.7 -1090.27,1475.7 -945.88,1331.31 -668.02,1331.31 -624.84,1288.13 -444.27,1288.13 -406.39,1250.25 -406.39,1201.08 -393.7,1188.39 U1.123@-393.7,1181.1
  Bottom w10: v1(-2704.72,716.54) -2728.35,740.16 -2728.35,1259.57 -2701.39,1286.53 -2599.3,1286.53 v1(-2590.55,1295.28)
USB2-DP: CON3.38 U1.124 | length 3117.6
  Top w10: v1(-2704.72,748.03) CON3.38@-2704.72,810.04 ; v1(-2590.55,1263.78) -2585.28,1269.05 -1861.99,1269.05 -1745.4,1385.64 -1585.06,1385.64 -1570.35,1385.64 -1541.07,1414.92 -1380.73,1414.92 -1333.99,1461.66 -1096.12,1461.66 -951.77,1317.31 -673.82,1317.31 -630.64,1274.13 -450.07,1274.13 -420.39,1244.45 -420.39,1201.51 -433.07,1188.82 U1.124@-433.07,1181.1
  Bottom w10: v1(-2704.72,748.03) -2714.35,757.65 -2714.35,1253.77 -2695.59,1272.53 -2599.3,1272.53 v1(-2590.55,1263.78)
USIM_CLK: CON3.12 D72.4 D72.7 J21.3 | length 529.5
  Top w6: J21.3@-2523.62,620.08 -2488.19,620.08 -2435.04,566.93 -2322.83,566.93 -2169.29,720.48 CON3.12@-2169.29,810.04
USIM_DATA: CON3.10 D72.2 D72.9 J21.7 | length 580.3
  Top w6: J21.7@-2523.62,570.08 -2515.16,570.08 -2512.01,566.93 -2500,566.93 -2460.63,527.56 D72.9@-2402.87,527.56 -2318.07,527.56 -2137.8,707.84 CON3.10@-2137.8,810.04
USIM_RST: CON3.14 D72.5 D72.6 J21.2 | length 706.3
  Top w6: J21.2@-2523.62,520.08 -2563.39,520.08 -2574.8,531.5 -2574.8,637.8 -2559.06,653.54 -2484.25,653.54 -2417.32,586.61 D72.5@-2368.79,586.61 -2350.39,586.61 -2200.79,736.22 CON3.14@-2200.79,810.04
USIM_VCC: CON3.8 D72.1 D72.10 J21.1 | length 672.8
  Top w6: J21.1@-2523.62,420.08 -2477.56,420.08 -2456.69,440.94 -2456.69,492.13 -2440.94,507.87 D72.10@-2402.87,507.87 -2299.21,507.87 -2106.3,700.79 CON3.8@-2106.3,810.04
VBUS1: CU2.2 CU3.2 D64.2 J20.1 J20.5 J22.4 J23.4 U13.1 | length 2068.8
  Top w6: D64.2@-2131.61,1625.98 -2093.77,1625.98 -2090.3,1622.51 -2086.82,1625.98 CU2.2@-2063.39,1625.98 ; -2091.43,1526.65 -2066.96,1526.65 -2062.99,1522.68 U13.1@-2062.99,1509.84 ; -2090.3,1569.76 -2089.19,1570.87 CU3.2@-2067.91,1570.87
  Top w60: J22.4@-2795.28,1625.98 -2731.09,1625.98 -2694.14,1662.93 -2694.14,2082.61 -2635.27,2141.49 -2166.29,2141.49 -2122.05,2097.24 J20.1@-2122.05,1775.59 -2122.05,1712.2 -2090.3,1680.45 -2090.3,1622.51 -2090.3,1569.76 -2091.43,1568.63 -2091.43,1526.65
  Bottom w60: J23.4@-2992.13,1625.98 J22.4@-2795.28,1625.98
VBUS-EN: RU1.2 U1.172 U13.4 | length 3310.9
  Top w6: U13.4@-1952.76,1435.04 -1947.83,1430.12 RU1.2@-1947.83,1385.83 -1897.64,1385.83 -1853.77,1429.69 v1(-1849.43,1435.39) ; U1.172@-787.4,-472.44 -744.09,-472.44 -641.73,-370.08 v1(-641.73,826.77)
  Bottom w6: v1(-1849.43,1435.39) -1534.81,1435.39 -1516.73,1417.31 -1516.73,912.76 -1442.55,838.58 -653.54,838.58 v1(-641.73,826.77)
VBUS-USB: C63.2 C65.1 C66.1 D63.1 J19.A4 J19.B4 U11.7 | length 849.7
  Top w11.81: J19.B4@114.17,2078.74 114.17,2122.05 133.86,2141.73 283.46,2141.73 303.15,2122.05 J19.A4@303.15,2078.74
  Top w12: 26.7,1731.3 U11.7@59.06,1731.3
  Top w25: C65.1@-30.51,1783.46 C65.1@-23.62,1776.57 ; C66.1@-7.48,1732.28 -7.48,1760.43 -19.68,1772.64 C65.1@-23.62,1776.57 ; 2.47,1984.65 -23.62,1958.56 C65.1@-23.62,1776.57 ; D63.1@82.68,1994.38 114.17,2025.87 J19.B4@114.17,2078.74
  Top w30: C66.1@-7.48,1732.28 -7.48,1731.3 26.7,1731.3 ; C63.2@31.5,1984.65 2.47,1984.65 12.2,1994.38 D63.1@82.68,1994.38
VCC-1V8: C20.2 Q9.1 Q10.1 Q11.1 R48.1 R49.1 R50.1 R54.1 R120.1 R229.1 R231.1 RA20.1 U5.2 | length 9594.8
  Top w6: v1(-1535.43,649.61) -1535.43,577.76 R231.1@-1476.38,518.7 ; Q11.1@-1438.88,692.54 -1438.88,651.48 v1(-1437.01,649.61) -1437.01,598.43 -1397.64,559.06 -1397.64,538.39 R229.1@-1377.95,518.7 ; Q10.1@-1316.83,692.54 -1314.96,690.67 v1(-1314.96,649.61) -1303.15,637.8 -1303.15,542.32 R120.1@-1279.53,518.7 ; Q9.1@-1190.85,692.54 -1190.85,686.91 -1188.98,685.04 v1(-1188.98,649.61) ; v1(-555.12,-1129.92) -555.12,-765.82 -263.78,-474.48 v1(-263.78,669.29) -263.78,1006.79 v1(-264.27,1006.79) ; R50.1@-429.13,-1374.61 v1(-429.13,-1338.58) ; v1(-374.02,-1338.58) -374.02,-1342.52 -377.95,-1346.46 R49.1@-377.95,-1374.61 R48.1@-326.77,-1374.61 ; -209.65,1775.59 -157.48,1775.59 -149.61,1767.72 -149.61,1732.28 -98.43,1681.1 -98.43,1539.37 v1(-19.68,1460.63) ; C20.2@-118.11,1981.3 -118.11,2008.97 -113.8,2013.28 U5.2@-113.8,2049.11 ; v1(964.42,-1254.6) 988.31,-1278.49 988.31,-1332.11 1049.33,-1393.14 1049.33,-1472.2 1205.59,-1628.46 1453.96,-1628.46 1736.28,-1346.14 2231.62,-1346.14 R54.1@2429.13,-1148.62
  Top w19.68: RA20.1@-209.65,1751.97 -209.65,1775.59 -209.65,1782.23 -92.43,1899.45 -92.43,1975.3 -98.43,1981.3 C20.2@-118.11,1981.3 ; U5.2@-113.8,2049.11 U5.2@-113.8,2055.12
  Bottom w6: v1(-1535.43,649.61) v1(-1437.01,649.61) v1(-1314.96,649.61) v1(-1188.98,649.61) -1094.49,649.61 -1074.8,669.29 -267.72,669.29 -265.75,667.32 v1(-263.78,669.29) ; v1(-374.02,-1338.58) v1(-429.13,-1338.58) -555.12,-1212.6 v1(-555.12,-1129.92) -529.06,-1103.86 626.89,-1103.86 744.75,-1221.73 880.19,-1221.73 913.06,-1254.6 v1(964.42,-1254.6) ; v1(-264.27,1006.79) -263.78,1114.17 -263.78,1330.71 -240.16,1354.33 -118.34,1354.33 -100.86,1336.85 -41.57,1336.85 -32.13,1327.41 -14.98,1327.41 -3.26,1339.12 -3.26,1444.21 v1(-19.68,1460.63)
VCC-3V3: C45.2 C61.1 C84.1 C87.1 D36.2 D56.2 D70.1 FB2.1 J4.2 J4.3 J5.2 J7.4 J14.1 J15.1 J16.3 J17.1 Q1.2 Q3.1 R17.1 R23.2 R24.2 R25.2 R27.1 R28.1 R31.1 R51.1 R52.1 R69.2 R77.1 R78.1 R79.1 R80.1 R87.2 R119.1 RA16.1 RA22.2 RA23.2 RA24.1 U42.9 | length 19931.1
  Top w6: R119.1@-1593.86,-1145.67 -1594.49,-1144.18 R119.1@-1594.49,-1133.86 ; R119.1@-1593.86,-1133.86 R119.1@-1594.49,-1133.86 ; R119.1@-1593.5,-1128.94 -1593.86,-1129.29 -1598.43,-1133.86 R119.1@-1594.49,-1133.86 ; D56.2@-1386.46,-988.19 -1386.46,-1019.06 -1374.02,-1031.5 -1311.02,-1031.5 -1294.29,-1048.23 R80.1@-1294.29,-1074.8 R79.1@-1294.29,-1106.3 R77.1@-1294.29,-1137.8 R78.1@-1294.29,-1169.29 ; v1(1118.11,1523.62) 1118.11,1551.18 1163.5,1596.57 R51.1@1163.5,1645.73 ; R69.2@1146.65,-929.13 1185.04,-929.13 1230.88,-883.29 v1(1250.18,-883.29) ; v1(1885.83,-1015.75) 1887.8,-1017.72 v1@1889.76,-1015.75 ; Q3.1@2007.5,-868.21 2019.69,-868.21 v1(2019.69,-905.51) 2071.85,-905.51 R87.2@2099.41,-877.95 ; v1(2253.94,-88.58) 2281.27,-88.58 R25.2@2281.27,-85.37 ; v1(2299.21,448.82) R27.1@2330.71,448.82 ; v1(2330.71,287.4) R28.1@2330.71,330.71 ; R31.1@2367.13,1066.93 R17.1@2367.13,1031.5 2381.8,1031.5 2385.74,1035.43 v1(2401.57,1035.43) ; v1(2417.32,1078.74) 2421.26,1078.74 2468.5,1031.5 J4.3@2507.87,1031.5 ; 2570.87,1031.5 v1(2578.74,1043.31)
  Top w10: U42.9@-2405.51,1363.98 -2383.66,1363.98 -2364.98,1345.3 -2267.11,1345.3 -2266.67,1344.86 -2248.45,1344.86 -2248.01,1345.3 -2218.87,1345.3 C87.1@-2198.91,1365.25 ; C87.1@-2199.8,1366.14 -2199.8,1365.25 C87.1@-2198.91,1365.25 ; C84.1@-2141.73,1393.31 -2166.36,1368.68 -2195.49,1368.68 C87.1@-2198.91,1365.25 ; RA16.1@-614.17,1810.04 -670.15,1810.04 -695.33,1784.85 -695.33,1488.71 -616.07,1409.45 v1(-610.24,1409.45) ; v1(-459.85,1389.15) -440.94,1408.06 RA24.1@-440.94,1412.4 ; RA23.2@-307.09,1412.4 RA23.2@-307.09,1412.4 -306.23,1412.4 v1(-306.23,1388.95) ; RA22.2@-255.91,1412.4 -130.17,1412.4 v1(-98.13,1380.36) ; R52.1@809.17,1645.73 807.09,1645.73 807.09,1622.39 v1(809.24,1622.39) ; R51.1@1163.5,1645.73 R51.1@1166.61,1645.73 ; v1(2255.95,-30.27) R24.2@2281.27,-30.25 ; v1(2261.64,-167.67) 2261.64,-149.17 2266.38,-144.43 R23.2@2281.27,-144.43
  Top w11.81: C84.1@-2141.73,1393.31 -2098.82,1350.39 -1893.7,1350.39 -1779.53,1464.57 -1599.96,1464.57 -1572.88,1491.65 -1416.52,1491.65 -1360.92,1547.24 -1070.24,1547.24 -931.72,1408.73 -685.72,1408.73 v1(-679.8,1414.65) ; v1(-610.24,1409.45) -610.24,1401.99 -574.14,1365.89 -483.11,1365.89 v1(-459.85,1389.15) ; v1(-43.31,1996.06) -51.18,1996.06 -51.18,1874.95 -100.73,1825.4 -100.73,1709.13 -82.68,1691.08 -82.68,1555.12 -11.09,1483.54 -10.2,1483.54 3.22,1470.12 3.22,1405.45 v1(-26.98,1375.25) ; R24.2@2281.27,-30.25 2281.27,-11.81 2289.15,-3.94 2389.76,-3.94 2401.57,-15.75 J5.2@2503.94,-15.75 ; J4.3@2507.87,1031.5 2570.87,1031.5 2570.87,1039.37 2559.06,1051.18 J4.2@2507.87,1051.18
  Top w12: Q1.2@1167.42,-1109.87 1195.55,-1109.87 1236.33,-1069.09 1373.97,-1069.09 1402.28,-1040.78 v1(1402.28,-883.08) ; J5.2@2503.94,-15.75 2724.41,-15.75 ; J4.2@2507.87,1051.18 J4.2@2507.87,1051.35
  Top w19.68: J15.1@-1842.52,-1369.69 -1755.32,-1369.69 -1645.14,-1259.5 -1586.2,-1259.5 -1563.44,-1236.74 -1563.44,-1182.59 -1593.86,-1152.17 R119.1@-1593.86,-1145.67 ; v1(889.76,1992.13) 891.73,1990.16 J7.4@891.73,1761.81 ; v1(1118.11,1523.62) 1118.11,1431.13 FB2.1@1130.92,1418.32
  Top w20: v1(1250.18,-883.29) 1250.18,-882.87 C61.1@1279.53,-882.87
  Top w23.62: J17.1@-1598.43,-976.38 -1398.27,-976.38 D56.2@-1386.46,-988.19
  Top w30: J7.4@891.73,1761.81 891.73,1680.47 D36.2@895.79,1680.47 941.98,1680.47 C45.2@948.82,1673.62
  Top w39.37: J17.1@-1598.43,-976.38 -1598.43,-1039.37 -1593.86,-1043.94 -1593.86,-1129.29 -1593.86,-1133.86 R119.1@-1593.86,-1145.67 ; v1(1885.83,-1015.75) 1885.83,-1264.48 1912.69,-1291.34 2178.59,-1291.34 2399.07,-1070.87 2575.25,-1070.87 2724.41,-921.7 2724.41,-15.75 v1(2724.41,118.11) v1(2724.41,149.61) ; v1@1889.76,-1015.75 v1(1913.39,-1015.75) D70.1@1954.62,-1015.75
  Bottom w6: v1(1913.39,-1015.75) 2007.87,-1015.75 2019.69,-1003.94 v1(2019.69,-905.51) ; v1(2401.57,1035.43) 2401.57,1059.06 2419.29,1076.77 v1(2417.32,1078.74)
  Bottom w10: v1@-26.98,1374.54 v1(-26.98,1375.25) ; v1(809.24,1622.39) 809.24,1700.79 821.06,1712.6 v1(889.76,1712.6) ; v1(2261.64,-167.67) 2255.95,-161.98 v1(2255.95,-30.27) 2255.95,43.35 2330.71,118.11 v1(2330.71,287.4) 2330.71,429.13 2311.02,448.82 v1(2299.21,448.82)
  Bottom w11.81: v1(-679.8,1414.65) -679.8,1413.39 -614.17,1413.39 v1(-610.24,1409.45) ; v1(-459.85,1389.15) -447.43,1401.57 -318.85,1401.57 v1(-306.23,1388.95) -299.17,1381.89 -100.99,1381.89 v1@-98.8,1379.69 ; v1(-98.13,1380.36) v1@-98.8,1379.69 ; v1(-26.98,1375.25) -27.42,1375.68 -39.37,1363.73 -82.83,1363.73 v1@-98.8,1379.69
  Bottom w19.68: J15.1@-1842.52,-1369.69 J14.1@-1590.55,-1369.69 -1539.63,-1369.69 -1446.85,-1462.47 -756.35,-1462.47 -724.41,-1494.41 J16.3@-724.41,-1594.49 ; v1(-43.31,1996.06) -43.31,2019.68 -3.94,2059.06 362.2,2059.06 425.2,1996.06 885.83,1996.06 v1(889.76,1992.13)
  Bottom w20: v1(1402.28,-883.08) 1462.21,-883.08 1462.31,-883.18 1462.24,-883.29 1460.38,-886.45
  Bottom w39.37: J17.1@-1598.43,-976.38 -1585.64,-989.17 -1102.36,-989.17 -1077.76,-964.57 -893.7,-964.57 -866.14,-992.13 314.96,-992.13 425.2,-881.89 1029.87,-881.89 1031.27,-883.29 v1(1250.18,-883.29) v1@1402.28,-883.29 ; v1(889.76,1712.6) 1078.74,1523.62 v1(1118.11,1523.62) 2098.43,1523.62 v1(2578.74,1043.31) 2661.42,960.63 2661.42,283.46 2724.41,220.47 v1(2724.41,149.61) v1(2724.41,118.11) ; v1(1402.28,-883.08) v1@1402.28,-883.29 ; v1(1913.39,-1015.75) v1(1885.83,-1015.75) 1759.84,-1015.75 1627.39,-883.29 1462.24,-883.29 v1@1402.28,-883.29
VCC_4G: C92.1 C93.1 C94.1 C99.1 C100.1 C101.1 C102.1 C103.1 CON3.2 CON3.24 CON3.39 CON3.41 CON3.52 D73.1 L7.2 R100.2 R117.1 | length 2892.9
  Top w6: D73.1@-2970,1311.02 -2807.09,1311.02 -2751.97,1255.91 CON3.41@-2751.97,1172.24 ; L7.2@-2169.29,232.28 -2110.95,232.28 -2106.62,236.61 C94.1@-2074.8,236.61 -1996.69,314.72 C101.1@-1996.69,259.84 C99.1@-1996.69,192.91 ; C92.1@-2058.07,433.07 R117.1@-2058.07,468.5 ; CON3.2@-2011.81,810.04 -1979.33,810.04 -1976.38,807.09
  Top w11.81: CON3.24@-2484.25,810.04 -2484.25,759.51 -2402.56,677.82 R100.2@-2402.56,665.35
  Top w23.62: CON3.52@-2925.2,810.04 -2925.2,893.7 ; CON3.24@-2484.25,810.04 -2484.25,872.37
  Top w25: -2925.2,893.7 -2925.2,917.32 -2917.32,925.2 ; CON3.41@-2751.97,1172.24 -2751.97,1108.86 -2745.47,1102.36 -2720.47,1102.36 CON3.39@-2720.47,1172.24
  Top w39.37: -2484.25,872.37 -2484.25,925.2
  Top w60: -2925.2,893.7 -2893.7,925.2 -2740.16,925.2 ; -2745.47,1102.36 -2740.16,1097.05 -2740.16,925.2 ; C100.1@-1996.69,456.69 -1996.69,562.36 -1976.38,582.68 -1976.38,807.09 -1976.38,874.02 -2027.56,925.2 -2484.25,925.2 -2740.16,925.2
VCOM: J4.1 R30.2 R36.1 | length 190.9
  Top w6: R30.2@2367.13,1141.73 R36.1@2367.13,1106.3 2448.82,1106.3 2484.25,1070.87 J4.1@2507.87,1070.87
VDD-CORE/HP-DET: CA11.1 RA11.1 UA1.35 | length 137.9
  Top w8: UA1.35@-298.04,1613.21 -273.1,1613.21
  Top w10: -273.1,1613.21 -241.13,1613.21 -222.66,1594.74 RA11.1@-210.3,1594.74 ; RA11.1@-209.65,1594.49 -210.3,1594.49 RA11.1@-210.3,1594.74 ; CA11.1@-209.65,1633.86 -211.59,1633.86 -210.62,1632.89 -210.3,1632.57 RA11.1@-210.3,1594.74
VGH: C31.1 C32.1 D27.2 J4.38 R29.2 R32.2 | length 1236.4
  Top w12: J4.38@2507.87,342.52 2574.8,342.52
  Top w19.68: C31.1@2515.75,1255.91 2515.75,1220.47 2531.1,1205.12 2708.66,1205.12 2720.47,1193.31 2720.47,476.38 2586.61,342.52 2574.8,342.52
VGL: C34.1 C35.1 D30.1 J4.35 R33.2 R37.2 | length 1282.1
  Top w6: v1(2232.28,1267.72) 2218.4,1229.22 2216.54,1224.06 C34.1@2220.83,1228.35 2250.98,1198.19 C35.1@2250.98,1177.17
  Top w12: J4.35@2507.87,401.57 2560.14,401.57 v1(2560.14,402.08)
  Bottom w19.68: v1(2232.28,1267.72) 2306.92,1267.72 2625.98,948.65 2625.98,444.88 2583.18,402.08 v1(2560.14,402.08)
VPP/VCC: CA10.1 RA7.2 RA8.1 UA1.15 | length 197.4
  Top w8: -531.17,1629.07 -527.95,1628.96 UA1.15@-498.82,1628.96
  Top w10: RA7.2@-597.44,1562.99 -601.75,1562.62 -601.75,1562.99 -601.75,1636.17 CA10.1@-597.44,1637.8 -582.16,1653.08 -555.56,1653.08 -531.55,1629.07 -531.17,1629.07
VRA1/MIC2P: CA2.1 UA1.14 | length 116
  Top w6: CA2.1@-597.44,1681.1 -597.44,1677.22 -559.91,1677.22 -527.4,1644.71 UA1.14@-498.82,1644.71
VRA2/MIC2N: CA3.2 RA2.2 UA1.13 | length 175.2
  Top w6: CA3.2@-597.44,1763.78 -597.44,1726.4 -603.37,1720.47 RA2.2@-597.44,1720.47 -567.51,1690.54 -556.25,1690.54 -526.17,1660.46 UA1.13@-498.82,1660.46
VRN/AGND: RA26.1 UA1.6 | length 113.4
  Top w8: UA1.6@-406.3,1721.48 -406.3,1750.75
  Top w10: RA26.1@-456.69,1810.04 -456.69,1805.45 -449.92,1805.45 -406.56,1762.09 -406.56,1751.22 -406.3,1750.97 -406.3,1750.75
VRP/AVCC: CA1.2 UA1.5 | length 108
  Top w8: UA1.5@-390.56,1721.48 -390.56,1754.02
  Top w10: CA1.2@-405.51,1814.57 -416.04,1804.04 -416.04,1794.27 -390.56,1768.79 -390.56,1754.02
W_DISABLE_N: CON3.20 R100.1 | length 168.5
  Top w11.81: CON3.20@-2421.26,810.04 -2421.26,731.57 -2367.56,677.88 -2367.56,666.89 -2369.09,666.89 R100.1@-2369.09,665.35
WAKEN: J12.54 Q9.3 R228.2 | length 317.5
  Top w6: R228.2@-1228.35,552.16 Q9.3@-1228.35,612.54 -1228.35,736.22 -1200.79,763.78 J12.54@-1200.79,858.26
